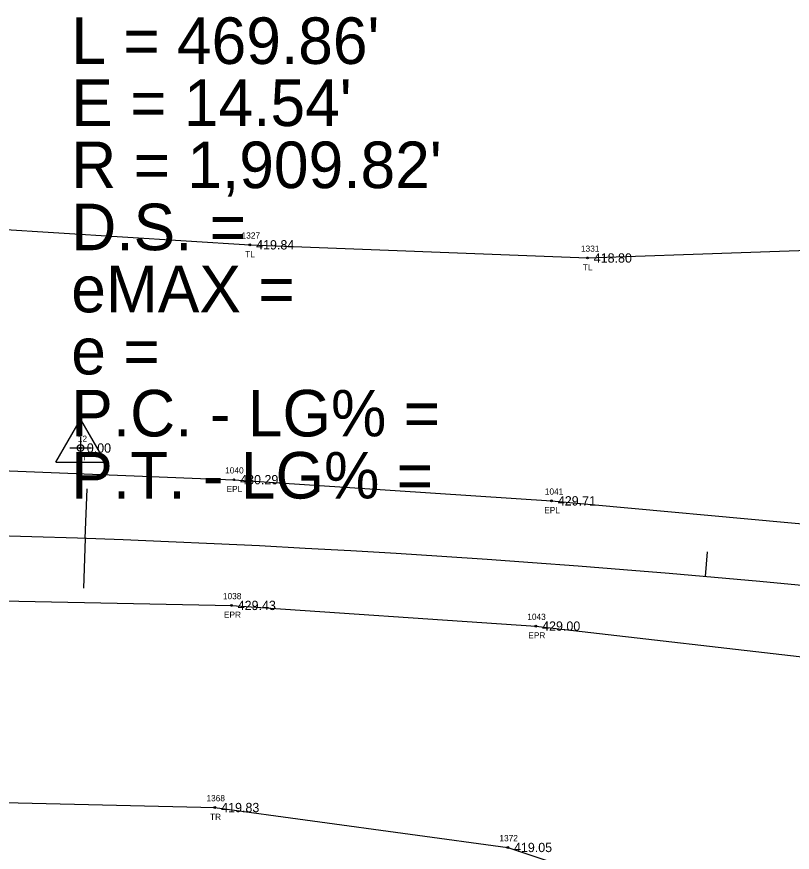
# Model space of a CAD drawing. Extents: x 1611114 to 1617038, y 769445 to 772083.
# Drawn here: x 1613757.2 to 1613882.1, y 771305 to 771439.6 of the extents above; entities that cross this region are included whole.
import ezdxf

# ---------------------------------------------------------------- set-up
doc = ezdxf.new("R2010")
doc.units = 0
for name, color, linetype in [('Default', 7, 'Continuous'), ('RD_EX_Road', 7, 'Continuous'), ('RD_EX_Road_txCode', 7, 'Continuous'), ('RD_EX_TX_Road_ELEV', 7, 'Continuous'), ('RD_EX_TX_VEG_ELEV', 7, 'Continuous'), ('RD_EX_VEG', 7, 'Continuous'), ('RD_EX_VEG_txCode', 7, 'Continuous'), ('RD_HC_Cl', 7, 'Continuous'), ('RD_HC_Data', 7, 'Continuous'), ('RD_HC_Data_Tic', 7, 'Continuous'), ('RD_HC_Survey_ELEV', 7, 'Continuous'), ('RD_HC_txCode', 7, 'Continuous'), ('RD_SMD_Locator', 7, 'Continuous')]:
    doc.layers.add(name, color=color, linetype=linetype)

msp = doc.modelspace()

# ---------------------------------------------------------------- linework, layer by layer
at = {"layer": 'Default'}
for p, q in [((1613767.5, 771371.89), (1613767.5, 771368.39)), ((1613769.25, 771370.14), (1613765.75, 771370.14))]:
    msp.add_line(p, q, dxfattribs=at)
msp.add_arc((1613700.84, 769446.93), 1909.82, 80.96676, 95.06271, dxfattribs=at)
msp.add_arc((1613700.84, 769446.93), 1909.82, 80.96676, 95.06271, dxfattribs=at)
at = {"layer": 'RD_EX_Road'}
for points in [[(1613192.48, 771329.15), (1613292.05, 771338.23), (1613391, 771348.45), (1613492.61, 771357.17), (1613541.86, 771361.21), (1613591.56, 771364.71), (1613642.92, 771366.4), (1613692.81, 771367.35), (1613742.66, 771367.02), (1613792.19, 771365.04), (1613843.32, 771361.63), (1613887.78, 771357.57), (1613892.3, 771358.63)], [(1613194.6, 771309.27), (1613294.55, 771318.15), (1613393.75, 771328.31), (1613493.74, 771336.74), (1613544.27, 771340.57), (1613593.48, 771343.76), (1613642.77, 771345.54), (1613692.58, 771346.11), (1613741.71, 771345.82), (1613791.79, 771344.79), (1613840.79, 771341.46), (1613889.25, 771335.84)]]:
    msp.add_lwpolyline(points, dxfattribs=at)
at = {"layer": 'RD_EX_VEG'}
for points in [[(1613190.16, 771350.86), (1613289.21, 771359.12), (1613387.94, 771369.51), (1613489.82, 771379.95), (1613503.78, 771396.75), (1613539.01, 771398.99), (1613588.71, 771402.91), (1613642.02, 771405.83), (1613690.35, 771406.29), (1613743.43, 771406.09), (1613794.76, 771402.87), (1613849.1, 771400.75), (1613898.57, 771402.5), (1614071.38, 771363.76), (1614171, 771346.54), (1614270.56, 771328.42), (1614365.98, 771308.81), (1614467.36, 771290.78), (1614565.75, 771274.12), (1614666.78, 771259.85)], [(1613196.47, 771290.95), (1613297.34, 771299.06), (1613395.35, 771312.89), (1613495.9, 771312.14), (1613544.51, 771308.67), (1613596.05, 771312.86), (1613644.8, 771313.72), (1613693.08, 771315.9), (1613741.59, 771313.35), (1613789.13, 771312.23), (1613836.26, 771305.8), (1613884.78, 771289.64), (1614061.95, 771273.87), (1614158.04, 771264.13), (1614253.51, 771253.52), (1614356.63, 771247.59), (1614457.77, 771232.22), (1614557.61, 771219.54), (1614658.3, 771205.52)]]:
    msp.add_lwpolyline(points, dxfattribs=at)
at = {"layer": 'RD_HC_Cl'}
msp.add_arc((1613700.84, 769446.93), 1909.82, 80.96676, 95.06271, dxfattribs=at)
at = {"layer": 'RD_HC_Data'}
for p, q in [((1613763.53, 771367.84), (1613767.5, 771374.72)), ((1613767.5, 771374.72), (1613771.47, 771367.84)), ((1613763.53, 771367.84), (1613771.47, 771367.84))]:
    msp.add_line(p, q, dxfattribs=at)
msp.add_circle((1613767.5, 771370.14), 0.529, dxfattribs=at)
at = {"layer": 'RD_HC_Data_Tic'}
for p, q in [((1613768.26, 771355.56), (1613768.54, 771363.56)), ((1613768.26, 771355.56), (1613767.97, 771347.57)), ((1613868.06, 771349.42), (1613868.41, 771353.4))]:
    msp.add_line(p, q, dxfattribs=at)
at = {"layer": 'RD_SMD_Locator'}
for centre in [(1613794.76, 771402.87), (1613849.1, 771400.75), (1613767.5, 771370.14), (1613792.19, 771365.04), (1613843.32, 771361.63), (1613791.79, 771344.79), (1613840.79, 771341.46), (1613789.13, 771312.23), (1613836.26, 771305.8)]:
    msp.add_circle(centre, 0.15, dxfattribs=at)

# ---------------------------------------------------------------- texts
at = {"layer": 'RD_EX_Road_txCode'}
for s, p in [('1040', (1613790.77, 771366.04)), ('EPL', (1613790.99, 771363.04)), ('1041', (1613842.22, 771362.63)), ('EPL', (1613842.12, 771359.63)), ('1038', (1613790.41, 771345.79)), ('EPR', (1613790.57, 771342.79)), ('1043', (1613839.4, 771342.46)), ('EPR', (1613839.56, 771339.46))]:
    msp.add_text(s, height=1, dxfattribs=at).set_placement(p)
at = {"layer": 'RD_EX_TX_Road_ELEV'}
for s, p in [('430.29', (1613793.19, 771364.29)), ('429.71', (1613844.32, 771360.88)), ('429.43', (1613792.79, 771344.04)), ('429.00', (1613841.79, 771340.71))]:
    msp.add_text(s, height=1.5, dxfattribs=at).set_placement(p)
at = {"layer": 'RD_EX_TX_VEG_ELEV'}
for s, p in [('419.84', (1613795.76, 771402.12)), ('418.80', (1613850.1, 771400)), ('419.83', (1613790.13, 771311.48)), ('419.05', (1613837.26, 771305.05))]:
    msp.add_text(s, height=1.5, dxfattribs=at).set_placement(p)
at = {"layer": 'RD_EX_VEG_txCode'}
for s, p in [('1327', (1613793.41, 771403.87)), ('1331', (1613848.04, 771401.75)), ('TL', (1613793.99, 771400.87)), ('TL', (1613848.33, 771398.75)), ('1368', (1613787.76, 771313.23)), ('TR', (1613788.33, 771310.23)), ('1372', (1613834.91, 771306.8))]:
    msp.add_text(s, height=1, dxfattribs=at).set_placement(p)
at = {"layer": 'RD_HC_Data'}
for s, p in [("L = 469.86'", (1613766, 771432)), ("E = 14.54'", (1613766, 771422)), ("R = 1,909.82'", (1613766, 771412)), ('D.S. = ', (1613766, 771402)), ('eMAX = ', (1613766, 771392)), ('e = ', (1613766, 771382)), ('P.C. - LG% = ', (1613766, 771372)), ('P.T. - LG% = ', (1613766, 771362))]:
    msp.add_text(s, height=7.5, dxfattribs=at).set_placement(p)
at = {"layer": 'RD_HC_Survey_ELEV'}
msp.add_text('0.00', height=1.5, dxfattribs=at).set_placement((1613768.5, 771369.39))
at = {"layer": 'RD_HC_txCode'}
for s, p in [('12', (1613767.05, 771371.14)), ('PI', (1613767.03, 771368.14))]:
    msp.add_text(s, height=1, dxfattribs=at).set_placement(p)

doc.saveas('drawing.dxf')
